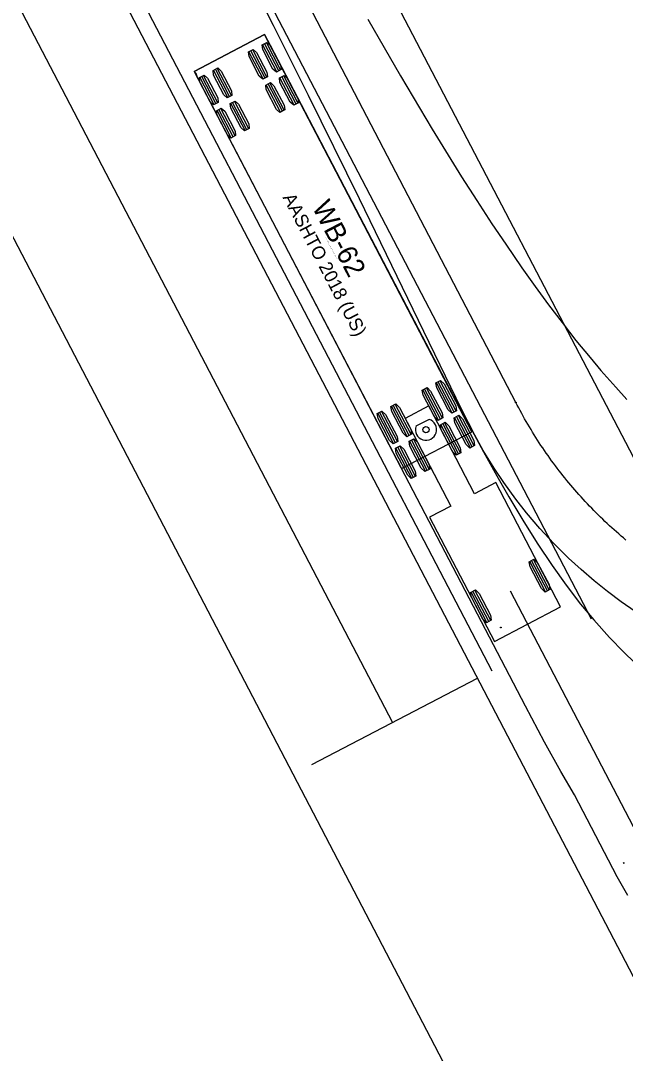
# Model space of a CAD drawing. Extents: x 2297881 to 2300600, y 559917 to 564426.
# Drawn here: x 2298908.1 to 2298972.8, y 562649.6 to 562760.2 of the extents above; entities that cross this region are included whole.
import ezdxf

# ---------------------------------------------------------------- set-up
doc = ezdxf.new("R2010")
doc.units = 0
for name, color, linetype in [('GE_X_Alignment', 7, 'Continuous'), ('PM_P_CL_Double_Solid', 7, 'Continuous'), ('PM_P_CL_Pass_Proh_Lt', 7, 'Continuous'), ('PM_P_Dotted_Line', 7, 'Continuous'), ('PM_P_Lane_Line', 7, 'Continuous'), ('SC_Scratch1', 7, 'Continuous'), ('SN_X_Public', 7, 'Continuous'), ('SV_X_Control_Cells_Found', 7, 'Continuous')]:
    doc.layers.add(name, color=color, linetype=linetype)

msp = doc.modelspace()

# ---------------------------------------------------------------- linework, layer by layer
at = {"layer": 'GE_X_Alignment'}
msp.add_line((2298386.28, 563783.36), (2299396.64, 561847.4), dxfattribs=at)
at = {"layer": 'PM_P_CL_Double_Solid'}
for p, q in [((2298934.2, 562758.76), (2298926.66, 562754.82)), ((2298935.51, 562754.76), (2298933.98, 562757.69)), ((2298935.71, 562754.87), (2298934.18, 562757.79)), ((2298956.4, 562716.2), (2298934.2, 562758.76)), ((2298935.91, 562754.97), (2298934.39, 562757.9)), ((2298934.04, 562754), (2298932.52, 562756.92)), ((2298934.25, 562754.1), (2298932.72, 562757.03)), ((2298934.45, 562754.21), (2298932.92, 562757.13)), ((2298926.66, 562754.82), (2298948.87, 562712.27)), ((2298929.19, 562751.46), (2298927.66, 562754.39)), ((2298930.25, 562752.01), (2298928.72, 562754.94)), ((2298930.45, 562752.12), (2298928.92, 562755.05)), ((2298930.65, 562752.23), (2298929.13, 562755.15)), ((2298937.76, 562751.43), (2298936.24, 562754.35)), ((2298928.78, 562751.25), (2298927.26, 562754.18)), ((2298928.99, 562751.36), (2298927.46, 562754.28)), ((2298935.9, 562750.45), (2298934.37, 562753.38)), ((2298936.1, 562750.56), (2298934.57, 562753.48)), ((2298936.3, 562750.66), (2298934.77, 562753.59)), ((2298937.36, 562751.21), (2298935.83, 562754.14)), ((2298937.56, 562751.32), (2298936.03, 562754.25)), ((2298932.1, 562748.47), (2298930.57, 562751.39)), ((2298932.3, 562748.57), (2298930.77, 562751.5)), ((2298932.5, 562748.68), (2298930.98, 562751.61)), ((2298930.63, 562747.71), (2298929.11, 562750.63)), ((2298930.84, 562747.81), (2298929.31, 562750.74)), ((2298931.04, 562747.92), (2298929.51, 562750.84)), ((2298954.29, 562718.22), (2298952.6, 562721.47)), ((2298954.5, 562718.33), (2298952.8, 562721.58)), ((2298954.7, 562718.43), (2298953, 562721.69)), ((2298952.83, 562717.46), (2298951.13, 562720.71)), ((2298953.03, 562717.57), (2298951.34, 562720.82)), ((2298953.24, 562717.67), (2298951.54, 562720.92)), ((2298949.48, 562715.71), (2298947.78, 562718.96)), ((2298949.68, 562715.82), (2298947.98, 562719.07)), ((2298949.88, 562715.92), (2298948.19, 562719.17)), ((2298951.78, 562718.98), (2298949.24, 562717.65)), ((2298956.68, 562709.58), (2298951.78, 562718.98)), ((2298948.01, 562714.95), (2298946.32, 562718.2)), ((2298948.22, 562715.05), (2298946.52, 562718.3)), ((2298948.42, 562715.16), (2298946.72, 562718.41)), ((2298956.44, 562714.61), (2298954.74, 562717.86)), ((2298956.64, 562714.71), (2298954.95, 562717.96)), ((2298949.24, 562717.65), (2298954.14, 562708.26)), ((2298951.82, 562717.54), (2298950.39, 562716.8)), ((2298954.77, 562713.74), (2298953.08, 562716.99)), ((2298954.98, 562713.84), (2298953.28, 562717.09)), ((2298955.18, 562713.95), (2298953.48, 562717.2)), ((2298956.24, 562714.5), (2298954.54, 562717.75)), ((2298948.87, 562712.27), (2298956.4, 562716.2)), ((2298956.4, 562716.2), (2298956.4, 562716.2)), ((2298950.16, 562711.33), (2298948.46, 562714.58)), ((2298950.36, 562711.43), (2298948.67, 562714.68)), ((2298951.42, 562711.99), (2298949.72, 562715.24)), ((2298951.62, 562712.09), (2298949.93, 562715.34)), ((2298951.83, 562712.2), (2298950.13, 562715.45)), ((2298949.96, 562711.22), (2298948.26, 562714.47)), ((2298958.96, 562710.77), (2298956.68, 562709.58)), ((2298965.9, 562697.47), (2298958.96, 562710.77)), ((2298954.14, 562708.26), (2298951.87, 562707.07)), ((2298951.87, 562707.07), (2298958.81, 562693.77)), ((2298964.49, 562699.18), (2298962.79, 562702.43)), ((2298964.69, 562699.29), (2298963, 562702.54)), ((2298964.29, 562699.07), (2298962.59, 562702.32)), ((2298958.01, 562695.8), (2298956.31, 562699.05)), ((2298958.21, 562695.9), (2298956.51, 562699.15)), ((2298958.41, 562696.01), (2298956.72, 562699.26)), ((2298960.5, 562699.17), (2298973.67, 562673.94)), ((2298958.81, 562693.77), (2298965.9, 562697.47)), ((2298965.9, 562697.47), (2298965.9, 562697.47))]:
    msp.add_line(p, q, dxfattribs=at)
for points in [[(2298973.09, 562666.55), (2298971.96, 562668.56), (2298967.39, 562677.32), (2298965.92, 562679.82), (2298964.17, 562682.99), (2298962.15, 562686.82), (2298927.32, 562753.56), (2298926.98, 562754.26), (2298926.87, 562754.58), (2298926.66, 562754.82), (2298934.2, 562758.76), (2298934.79, 562757.61)], [(2298934.79, 562757.61), (2298954.4, 562720.09), (2298957.63, 562714.06), (2298959.06, 562711.5), (2298960.35, 562709.25), (2298961.84, 562706.74), (2298963.39, 562704.28), (2298965, 562701.88), (2298966.48, 562699.79), (2298968.04, 562697.77), (2298969.45, 562696.06), (2298971.13, 562694.18), (2298972.67, 562692.6), (2298973.8, 562691.52)]]:
    msp.add_lwpolyline(points, dxfattribs=at)
for points in [[(2298935.96, 562755), (2298935.46, 562754.73), (2298935.09, 562755.06), (2298933.99, 562757.17), (2298933.93, 562757.66), (2298934.44, 562757.92), (2298934.8, 562757.59), (2298935.9, 562755.49)], [(2298934.5, 562754.24), (2298933.99, 562753.97), (2298933.63, 562754.3), (2298932.53, 562756.41), (2298932.47, 562756.9), (2298932.97, 562757.16), (2298933.34, 562756.83), (2298934.44, 562754.72)], [(2298929.24, 562751.49), (2298928.73, 562751.23), (2298928.37, 562751.56), (2298927.27, 562753.66), (2298927.21, 562754.15), (2298927.71, 562754.42), (2298928.08, 562754.09), (2298929.18, 562751.98)], [(2298930.7, 562752.25), (2298930.2, 562751.99), (2298929.83, 562752.32), (2298928.73, 562754.42), (2298928.67, 562754.91), (2298929.18, 562755.18), (2298929.54, 562754.85), (2298930.64, 562752.74)], [(2298937.81, 562751.45), (2298937.31, 562751.19), (2298936.94, 562751.52), (2298935.84, 562753.62), (2298935.78, 562754.11), (2298936.29, 562754.38), (2298936.65, 562754.05), (2298937.75, 562751.94)], [(2298936.35, 562750.69), (2298935.84, 562750.42), (2298935.48, 562750.75), (2298934.38, 562752.86), (2298934.32, 562753.35), (2298934.82, 562753.61), (2298935.19, 562753.28), (2298936.29, 562751.18)], [(2298932.55, 562748.71), (2298932.05, 562748.44), (2298931.68, 562748.77), (2298930.58, 562750.88), (2298930.52, 562751.37), (2298931.03, 562751.63), (2298931.39, 562751.3), (2298932.49, 562749.2)], [(2298931.09, 562747.94), (2298930.58, 562747.68), (2298930.22, 562748.01), (2298929.12, 562750.12), (2298929.06, 562750.6), (2298929.56, 562750.87), (2298929.93, 562750.54), (2298931.03, 562748.43)], [(2298954.75, 562718.46), (2298954.24, 562718.2), (2298953.85, 562718.57), (2298952.63, 562720.91), (2298952.55, 562721.45), (2298953.05, 562721.71), (2298953.44, 562721.34), (2298954.67, 562719)], [(2298953.29, 562717.7), (2298952.78, 562717.43), (2298952.39, 562717.81), (2298951.17, 562720.15), (2298951.08, 562720.68), (2298951.59, 562720.95), (2298951.98, 562720.57), (2298953.2, 562718.23)], [(2298949.93, 562715.95), (2298949.43, 562715.68), (2298949.04, 562716.06), (2298947.81, 562718.4), (2298947.73, 562718.93), (2298948.24, 562719.2), (2298948.63, 562718.82), (2298949.85, 562716.48)], [(2298948.47, 562715.18), (2298947.96, 562714.92), (2298947.57, 562715.29), (2298946.35, 562717.64), (2298946.27, 562718.17), (2298946.77, 562718.43), (2298947.16, 562718.06), (2298948.39, 562715.72)], [(2298956.69, 562714.74), (2298956.19, 562714.47), (2298955.8, 562714.85), (2298954.57, 562717.19), (2298954.49, 562717.72), (2298955, 562717.99), (2298955.39, 562717.61), (2298956.61, 562715.27)], [(2298955.23, 562713.97), (2298954.72, 562713.71), (2298954.33, 562714.09), (2298953.11, 562716.43), (2298953.03, 562716.96), (2298953.53, 562717.23), (2298953.92, 562716.85), (2298955.15, 562714.51)], [(2298950.41, 562711.46), (2298949.91, 562711.2), (2298949.52, 562711.57), (2298948.3, 562713.91), (2298948.21, 562714.45), (2298948.72, 562714.71), (2298949.11, 562714.34), (2298950.33, 562712)], [(2298951.88, 562712.22), (2298951.37, 562711.96), (2298950.98, 562712.33), (2298949.76, 562714.68), (2298949.67, 562715.21), (2298950.18, 562715.47), (2298950.57, 562715.1), (2298951.79, 562712.76)], [(2298964.74, 562699.31), (2298964.24, 562699.05), (2298963.85, 562699.42), (2298962.63, 562701.76), (2298962.54, 562702.3), (2298963.05, 562702.56), (2298963.44, 562702.19), (2298964.66, 562699.85)], [(2298958.46, 562696.03), (2298957.96, 562695.77), (2298957.57, 562696.15), (2298956.35, 562698.49), (2298956.26, 562699.02), (2298956.77, 562699.29), (2298957.16, 562698.91), (2298958.38, 562696.57)]]:
    msp.add_lwpolyline(points, close=True, dxfattribs=at)
for centre, radius in [((2298951.48, 562716.45), 0.34), ((2298959.5, 562695.26), 0.0417), ((2298972.66, 562670.03), 0.0417), ((2298972.66, 562670.03), 0.0417)]:
    msp.add_circle(centre, radius, dxfattribs=at)
msp.add_arc((2298951.48, 562716.45), 1.14, 162.5598, 72.5598, dxfattribs=at)
at = {"layer": 'PM_P_CL_Pass_Proh_Lt'}
msp.add_line((2298832.69, 562957.71), (2298969.18, 562696.18), dxfattribs=at)
at = {"layer": 'PM_P_Dotted_Line'}
msp.add_line((2298822.05, 562952.16), (2298958.54, 562690.63), dxfattribs=at)
at = {"layer": 'PM_P_Lane_Line'}
for p, q in [((2298467.65, 563579.35), (2299376.95, 561837.04)), ((2298843.32, 562963.26), (2299419.43, 561859.39))]:
    msp.add_line(p, q, dxfattribs=at)
at = {"layer": 'SC_Scratch1'}
msp.add_line((2298939.26, 562680.57), (2298956.99, 562689.82), dxfattribs=at)
at = {"layer": 'SN_X_Public'}
msp.add_line((2298961.1, 562719.36), (2298916.3, 562805.32), dxfattribs=at)
for points in [[(2298973.9, 562696.98), (2298972.4, 562698.02), (2298970.93, 562699.11), (2298969.5, 562700.26), (2298968.11, 562701.45), (2298966.76, 562702.69), (2298965.19, 562704.25), (2298963.69, 562705.87), (2298962.26, 562707.55), (2298961.12, 562709), (2298959.82, 562710.79), (2298958.79, 562712.33), (2298957.62, 562714.22), (2298956.71, 562715.84), (2298956.02, 562717.16), (2298954.72, 562719.82), (2298944.37, 562741.16), (2298938.88, 562752.25), (2298935.14, 562759.72), (2298931.07, 562767.76)], [(2298945.27, 562760.4), (2298948.76, 562754.35), (2298952.16, 562748.63), (2298955.3, 562743.53), (2298956.91, 562741), (2298958.55, 562738.49), (2298960.02, 562736.3), (2298961.76, 562733.78), (2298963.17, 562731.79), (2298964.6, 562729.83), (2298966.06, 562727.91), (2298967.54, 562726.01), (2298969.06, 562724.16), (2298970.22, 562722.79), (2298971.8, 562721.01), (2298973.01, 562719.69)], [(2298972.89, 562704.62), (2298972.64, 562704.84), (2298972.38, 562705.05), (2298972.13, 562705.27), (2298971.88, 562705.49), (2298971.63, 562705.71), (2298971.39, 562705.94), (2298971.14, 562706.16), (2298970.9, 562706.39), (2298970.65, 562706.62), (2298970.41, 562706.85), (2298970.17, 562707.08), (2298969.93, 562707.31), (2298969.7, 562707.55), (2298969.46, 562707.78), (2298969.23, 562708.02), (2298969, 562708.26), (2298968.77, 562708.5), (2298968.54, 562708.75), (2298968.32, 562708.99), (2298968.09, 562709.24), (2298967.87, 562709.49), (2298967.65, 562709.74), (2298967.43, 562709.99), (2298967.21, 562710.24), (2298967, 562710.5), (2298966.78, 562710.75), (2298966.57, 562711.01), (2298966.36, 562711.27), (2298966.15, 562711.53), (2298965.95, 562711.79), (2298965.74, 562712.05), (2298965.54, 562712.32), (2298965.34, 562712.58), (2298965.14, 562712.85), (2298964.94, 562713.12), (2298964.75, 562713.39), (2298964.55, 562713.66), (2298964.36, 562713.94), (2298964.17, 562714.21), (2298963.99, 562714.49), (2298963.8, 562714.76), (2298963.62, 562715.04), (2298963.44, 562715.32), (2298963.26, 562715.6), (2298963.08, 562715.88), (2298962.9, 562716.17), (2298962.73, 562716.45), (2298962.56, 562716.74), (2298962.39, 562717.02), (2298962.22, 562717.31), (2298962.05, 562717.6), (2298961.89, 562717.89), (2298961.73, 562718.18), (2298961.57, 562718.48), (2298961.41, 562718.77), (2298961.26, 562719.06), (2298961.1, 562719.36)]]:
    msp.add_lwpolyline(points, dxfattribs=at)
msp.add_circle((2298961.1, 562719.36), 0.0417, dxfattribs=at)
at = {"layer": 'SV_X_Control_Cells_Found'}
msp.add_line((2298478.28, 563584.91), (2298947.9, 562685.08), dxfattribs=at)

# ---------------------------------------------------------------- texts
at = {"layer": 'PM_P_CL_Double_Solid'}
for s, height, p in [('AASHTO 2018 (US)', 1.4167, (2298936.1, 562741.32)), ('WB-62', 2.125, (2298939.23, 562740.3)), ('(c) 2021 Transoft Solutions, Inc. All rights reserved.', 0.085, (2298940.69, 562737.03))]:
    msp.add_text(s, height=height, rotation=297.5598, dxfattribs=at).set_placement(p)

doc.saveas('drawing.dxf')
